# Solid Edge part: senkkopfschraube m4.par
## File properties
Title: Senkkopfschraube M4
Subject: Schmiege
Author: rauh
Template: Normal.par
Last saved by: administrator
Revision: 4
Application: Solid Edge
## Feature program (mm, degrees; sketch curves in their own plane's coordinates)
sketch for "unnamed Protrusion 1" plane through (0, 0, 0) normal (0, 0, 1) x-axis (1, 0, 0)
  circle centre (0, 0) radius 2
extrude "unnamed Protrusion 1" add finite 9 along +normal
sketch for "unnamed RevolvedProtrusion 1" plane through (0, 0, 0) normal (0, -1, 0) x-axis (1, 0, 0)
  line (2, 9) -> (5, 12)
  line (5, 12) -> (0, 12)
  line (2, 9) -> (0, 9)
revolve "unnamed RevolvedProtrusion 1" add full turn 360 deg about sketch line (0, 9) -> (0, 12)
sketch for "unnamed Cutout 1" plane through (0, 0, 0) normal (0, -1, 0) x-axis (1, 0, 0)
  line (-5, 12) -> (-0.5, 12)
  line (-0.5, 12) -> (-0.5, 10)
  line (-0.5, 10) -> (0.5, 10)
  line (0.5, 10) -> (0.5, 12)
extrude "unnamed Cutout 1" cut finite 107.95 symmetric
thread "unnamed Thread 1"
